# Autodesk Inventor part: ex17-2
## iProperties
Created: 2006-04
Part Number: ex17-2
Project: EVERGREEN VALLEY COLLEGE
Description: SWIVEL
Document SubType Name: Modeling
Designer: E. MOSS
Authority: MS. TEACHER
Author: E. MOSS
Revision Number: A
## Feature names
1. Extrusion1
2. Extrusion2
3. Hole1
4. Hole2
